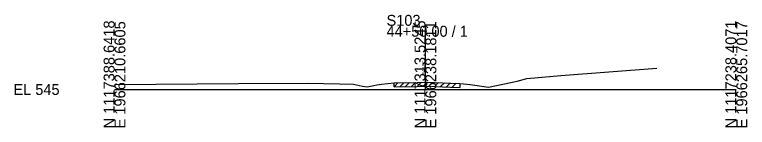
# Model space of a CAD drawing. Extents: x -26 to 163, y -10 to 45020.
# Drawn here: x -25.7 to 162.8, y 4490.3 to 4519.2 of the extents above; entities that cross this region are included whole.
import ezdxf

# ---------------------------------------------------------------- set-up
doc = ezdxf.new("R2010")
doc.units = 0
for name, color, linetype in [('RD_GPK_XS_Cell', 7, 'Continuous'), ('RD_XS_ExGround', 7, 'Continuous'), ('RD_XS_ExPaveRet', 7, 'Continuous'), ('RD_XS_TX_Elev_EX', 7, 'Continuous')]:
    doc.layers.add(name, color=color, linetype=linetype)

msp = doc.modelspace()

# ---------------------------------------------------------------- linework, layer by layer
at = {"layer": 'RD_GPK_XS_Cell'}
for p, q in [((80, 4500), (80, 4516.32)), ((0, 4500), (80, 4500)), ((80, 4500), (160, 4500))]:
    msp.add_line(p, q, dxfattribs=at)
at = {"layer": 'RD_XS_ExGround'}
for p, q in [((114.87, 4503.56), (139.58, 4505.44)), ((103.6, 4502.15), (106.08, 4502.82)), ((106.08, 4502.82), (114.87, 4503.56)), ((0, 4501.25), (31.87, 4501.57)), ((31.87, 4501.57), (49.66, 4501.58)), ((49.66, 4501.58), (57.92, 4501.43)), ((57.92, 4501.43), (61.5, 4501.35)), ((61.5, 4501.35), (63.85, 4500.85)), ((63.85, 4500.85), (65, 4500.64)), ((65, 4500.64), (66.73, 4501.05)), ((66.73, 4501.05), (67.46, 4501.23)), ((67.46, 4501.23), (68.72, 4501.34)), ((68.72, 4501.34), (71.92, 4501.67)), ((71.92, 4501.67), (77.85, 4501.8)), ((77.85, 4501.8), (80, 4501.87)), ((80, 4501.87), (80.39, 4501.88)), ((80.39, 4501.88), (86.48, 4501.63)), ((86.48, 4501.63), (88.9, 4501.53)), ((88.9, 4501.53), (89.76, 4501.45)), ((89.76, 4501.45), (91.52, 4501.29)), ((91.52, 4501.29), (92.76, 4501.09)), ((92.76, 4501.09), (96.23, 4500.62)), ((96.23, 4500.62), (103.6, 4502.15))]:
    msp.add_line(p, q, dxfattribs=at)
at = {"layer": 'RD_XS_ExPaveRet'}
for p, q in [((71.92, 4500.67), (72.94, 4501.69)), ((71.92, 4500.67), (71.92, 4501.67)), ((71.92, 4500.67), (77.85, 4500.8)), ((73.42, 4500.7), (74.44, 4501.72)), ((74.92, 4500.74), (75.94, 4501.76)), ((76.42, 4500.77), (77.44, 4501.79)), ((77.85, 4500.8), (80, 4500.87)), ((77.92, 4500.8), (78.95, 4501.83)), ((79.42, 4500.85), (80.45, 4501.87)), ((80, 4500.87), (80.39, 4500.88)), ((80.39, 4500.88), (86.48, 4500.63)), ((80.92, 4500.86), (81.88, 4501.82)), ((82.42, 4500.8), (83.38, 4501.76)), ((83.92, 4500.74), (84.88, 4501.7)), ((85.42, 4500.68), (86.39, 4501.64)), ((86.48, 4500.63), (88.9, 4500.53)), ((86.92, 4500.62), (87.88, 4501.58)), ((88.9, 4501.53), (88.9, 4500.53))]:
    msp.add_line(p, q, dxfattribs=at)

# ---------------------------------------------------------------- texts
at = {"layer": 'RD_GPK_XS_Cell'}
for s, p in [('S103', (70, 4516.32)), ('44+50.00 / 1', (70, 4513.52)), ('EL 545', (-26, 4498.6))]:
    msp.add_text(s, height=2.8, dxfattribs=at).set_placement(p)
for s, p in [('N 1117388.6418', (0, 4490)), ('E 1966210.6605', (2.8, 4490)), ('N 1117313.5245', (80, 4490)), ('E 1966238.1811', (82.8, 4490)), ('N 1117238.4071', (160, 4490)), ('E 1966265.7017', (162.8, 4490))]:
    msp.add_text(s, height=2.8, rotation=90, dxfattribs=at).set_placement(p)
at = {"layer": 'RD_XS_TX_Elev_EX'}
msp.add_text('546.87', height=0.8, rotation=90, dxfattribs=at).set_placement((79.9, 4503.87))

doc.saveas('drawing.dxf')
